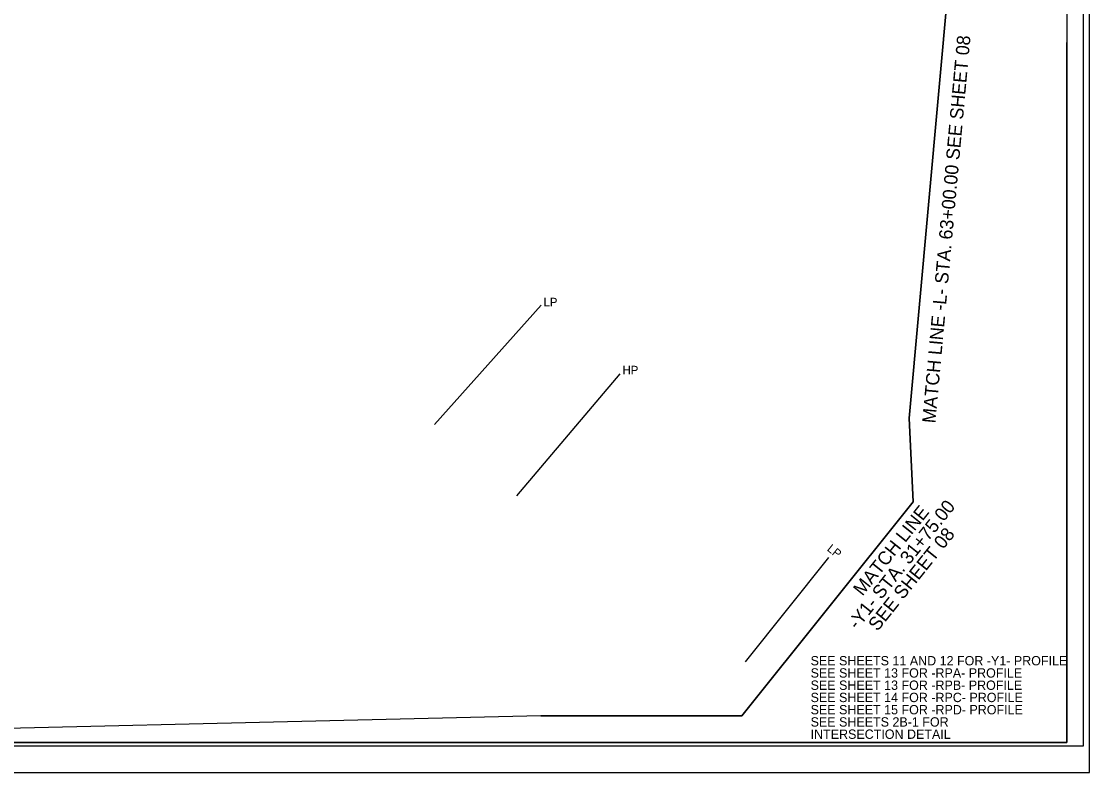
# Model space of a CAD drawing. Extents: x 1639431 to 1641888, y 841916 to 843940.
# Drawn here: x 1641087 to 1641888, y 841916 to 842479 of the extents above; entities that cross this region are included whole.
import ezdxf

# ---------------------------------------------------------------- set-up
doc = ezdxf.new("R2010")
doc.units = 0
for name, color, linetype in [('Matchline', 7, 'Continuous'), ('Matchline Text', 7, 'Continuous'), ('Old_Level_1', 7, 'Continuous'), ('Prop Dimension', 7, 'Continuous'), ('Sheet Clip Boundary CELL', 7, 'Continuous'), ('Sheet Cutting Line CELL', 7, 'Continuous'), ('Sheet Plan CELL', 7, 'Continuous'), ('Sheet Plot Border Inside CELL', 7, 'Continuous'), ('Sheet Plot Border Outside CELL', 7, 'Continuous')]:
    doc.layers.add(name, color=color, linetype=linetype)

msp = doc.modelspace()

# ---------------------------------------------------------------- linework, layer by layer
at = {"layer": 'Matchline'}
msp.add_line((1641476.31, 841958.82), (1641627.07, 841958.82), dxfattribs=at)
msp.add_lwpolyline([(1641627.07, 841958.82), (1641755.49, 842119.21), (1641752.38, 842181.83), (1641796.56, 842667.29)], dxfattribs=at)
at = {"layer": 'Old_Level_1'}
for p, q in [((1641396.6, 842177.18), (1641476.53, 842266.68)), ((1641458.17, 842123.65), (1641535.69, 842215.25)), ((1641629.83, 841999.24), (1641692.16, 842077.45))]:
    msp.add_line(p, q, dxfattribs=at)
at = {"layer": 'Sheet Clip Boundary CELL'}
for points in [[(1641443.85, 842919.31), (1641444.34, 842714.97), (1641747.5, 842714.54), (1641796.56, 842667.29), (1641752.38, 842181.83), (1641755.49, 842119.21), (1641627.07, 841958.82)], [(1641627.07, 841958.82), (1641476.31, 841958.82), (1640885.35, 841944.88), (1640879.04, 842022.1), (1640881.13, 842043.37), (1640760.23, 842041.75), (1640760.69, 842110.15), (1640760.04, 842113.92), (1640759.14, 842119.04), (1640760.54, 842128.84), (1640539.36, 842129.01), (1640414.85, 842129.76)]]:
    msp.add_lwpolyline(points, dxfattribs=at)
at = {"layer": 'Sheet Cutting Line CELL'}
msp.add_line((1640204.3, 841916.31), (1641887.8, 841916.31), dxfattribs=at)
at = {"layer": 'Sheet Plan CELL'}
for points in [[(1640370.79, 841938.82), (1640370.76, 842988.79), (1641670.75, 842988.83), (1641670.76, 842838.77), (1641870.8, 842838.76), (1641870.8, 841938.82)], [(1641870.83, 842988.82), (1640370.79, 842988.82), (1640370.79, 841938.82), (1641870.8, 841938.82)]]:
    msp.add_lwpolyline(points, close=True, dxfattribs=at)
at = {"layer": 'Sheet Plot Border Inside CELL'}
msp.add_lwpolyline([(1640217.3, 841936.31), (1641883.29, 841936.32), (1641883.3, 842991.31), (1640217.3, 842991.31)], close=True, dxfattribs=at)
at = {"layer": 'Sheet Plot Border Outside CELL'}
msp.add_lwpolyline([(1640204.3, 841916.31), (1641887.8, 841916.31), (1641887.8, 843011.31), (1640204.3, 843011.31)], close=True, dxfattribs=at)
msp.add_lwpolyline([(1640204.3, 841916.31), (1641887.8, 841916.31), (1641887.8, 843011.31), (1640204.3, 843011.31)], close=True, dxfattribs=at)

# ---------------------------------------------------------------- texts
at = {"layer": 'Matchline Text'}
for s, rotation, p in [('MATCH LINE -L- STA. 63+00.00 SEE SHEET 08', 84.80047, (1641772.11, 842177.86)), ('-Y1- STA. 31+75.00', 51.31933, (1641713.5, 842022.95)), ('MATCH LINE', 51.31933, (1641717.43, 842048.14)), ('SEE SHEET 08', 51.31933, (1641728.73, 842021.69))]:
    msp.add_text(s, height=10, rotation=rotation, dxfattribs=at).set_placement(p)
at = {"layer": 'Old_Level_1'}
for s, rotation, p in [('LP', 360, (1641478.32, 842265.76)), ('HP', 360, (1641537.56, 842214.79)), ('LP', 321.44605, (1641690.41, 842083.11))]:
    msp.add_text(s, height=6.375, rotation=rotation, dxfattribs=at).set_placement(p)
at = {"layer": 'Prop Dimension'}
for s, p in [('SEE SHEETS 11 AND 12 FOR -Y1- PROFILE', (1641678.57, 841996.68)), ('SEE SHEET 13 FOR -RPA- PROFILE', (1641678.57, 841987.51)), ('SEE SHEET 13 FOR -RPB- PROFILE', (1641678.57, 841978.33)), ('SEE SHEET 14 FOR -RPC- PROFILE', (1641678.57, 841969.15)), ('SEE SHEET 15 FOR -RPD- PROFILE', (1641678.57, 841959.98)), ('SEE SHEETS 2B-1 FOR', (1641678.57, 841950.8)), ('INTERSECTION DETAIL', (1641678.57, 841941.62))]:
    msp.add_text(s, height=7, rotation=360, dxfattribs=at).set_placement(p)

doc.saveas('drawing.dxf')
